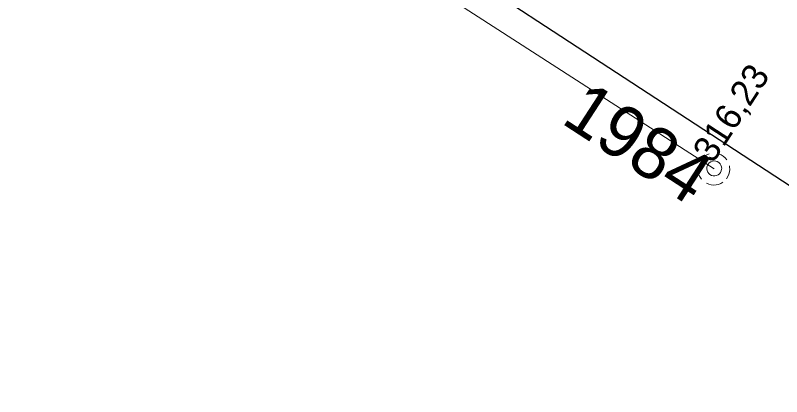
# Model space of a CAD drawing. Extents: x -742876 to -742577, y -1054710 to -1054452.
# Drawn here: x -742642.52 to -742618.85, y -1054551.73 to -1054539.95 of the extents above; entities that cross this region are included whole.
import ezdxf

# ---------------------------------------------------------------- set-up
doc = ezdxf.new("R2010")
doc.units = 0
doc.header["$LTSCALE"] = 0.36
doc.linetypes.add('MEDIUM_DASHED', pattern=[4.5, 3, -1.5])
for name, color, linetype, lineweight in [('1', 7, 'MEDIUM_DASHED', 25), ('18', 7, 'Continuous', 13), ('20', 7, 'Continuous', 13), ('8', 7, 'Continuous', 13)]:
    doc.layers.add(name, color=color, linetype=linetype, lineweight=lineweight)

msp = doc.modelspace()

# ---------------------------------------------------------------- linework, layer by layer
at = {"layer": '18'}
for points in [[(-742621.083, -1054544.227), (-742621.154, -1054544.255), (-742621.221, -1054544.294), (-742621.281, -1054544.342), (-742621.332, -1054544.399), (-742621.356, -1054544.433)], [(-742620.542, -1054544.41), (-742620.592, -1054544.352), (-742620.65, -1054544.302), (-742620.715, -1054544.261), (-742620.786, -1054544.232), (-742620.835, -1054544.218)], [(-742621.428, -1054544.619), (-742621.434, -1054544.696), (-742621.429, -1054544.773), (-742621.412, -1054544.848), (-742621.383, -1054544.919), (-742621.343, -1054544.985), (-742621.327, -1054545.007)], [(-742620.547, -1054544.996), (-742620.506, -1054544.931), (-742620.475, -1054544.861), (-742620.456, -1054544.786), (-742620.448, -1054544.71), (-742620.453, -1054544.633), (-742620.459, -1054544.598)], [(-742621.17, -1054545.136), (-742621.1, -1054545.167), (-742621.025, -1054545.186), (-742620.949, -1054545.193), (-742620.872, -1054545.188), (-742620.797, -1054545.171), (-742620.725, -1054545.143), (-742620.665, -1054545.108)]]:
    msp.add_lwpolyline(points, dxfattribs=at)
msp.add_lwpolyline([(-742620.699, -1054544.679), (-742620.705, -1054544.627), (-742620.723, -1054544.577), (-742620.751, -1054544.533), (-742620.789, -1054544.496), (-742620.834, -1054544.469), (-742620.884, -1054544.453), (-742620.936, -1054544.448), (-742620.988, -1054544.455), (-742621.037, -1054544.474), (-742621.081, -1054544.504), (-742621.116, -1054544.543), (-742621.142, -1054544.588), (-742621.157, -1054544.639), (-742621.16, -1054544.691), (-742621.152, -1054544.743), (-742621.131, -1054544.791), (-742621.101, -1054544.834), (-742621.061, -1054544.869), (-742621.015, -1054544.893), (-742620.964, -1054544.907), (-742620.912, -1054544.909), (-742620.86, -1054544.899), (-742620.812, -1054544.877), (-742620.77, -1054544.845), (-742620.737, -1054544.805), (-742620.713, -1054544.758), (-742620.701, -1054544.707)], close=True, dxfattribs=at)
at = {"layer": '20'}
msp.add_lwpolyline([(-742620.93, -1054544.69), (-742629.588, -1054539.108), (-742635.043, -1054535.591), (-742649.41, -1054526.33)], dxfattribs=at)
msp.add_lwpolyline([(-742620.93, -1054544.69), (-742629.588, -1054539.108), (-742635.043, -1054535.591), (-742649.41, -1054526.33)], dxfattribs=at)
at = {"layer": '8', "lineweight": 25}
msp.add_lwpolyline([(-742635.66, -1054534.06), (-742617.61, -1054545.851), (-742608.91, -1054551.54), (-742608.609, -1054551.73), (-742608.42, -1054551.429)], dxfattribs=at)

# ---------------------------------------------------------------- texts
at = {"layer": '1'}
for s, height, rotation, p in [('316,23', 0.8, 57, (-742620.97, -1054544.548)), ('1984', 1.6, 327, (-742625.7, -1054543.253))]:
    msp.add_text(s, height=height, rotation=rotation, dxfattribs=at).set_placement(p)

doc.saveas('drawing.dxf')
